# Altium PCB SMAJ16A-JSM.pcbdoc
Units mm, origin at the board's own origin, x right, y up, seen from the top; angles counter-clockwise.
Board outline 19.08 x 15.58 mm, 2 copper layers (Top Layer, Bottom Layer), stack 0 mm thick; 1 components, 0 nets, 2 pads, 0 vias.
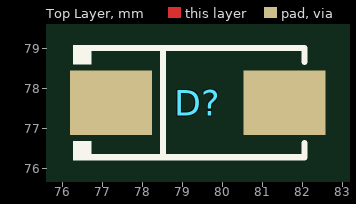
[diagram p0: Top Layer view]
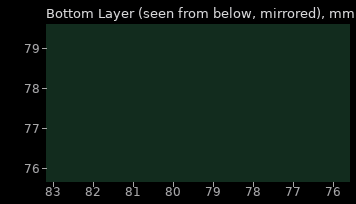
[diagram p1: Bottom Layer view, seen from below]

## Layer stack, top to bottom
Top Layer: signal copper (thickness not stored)
Bottom Layer: signal copper (thickness not stored)

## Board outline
88.935,69.85 69.85,69.85 69.85,85.43 88.935,85.43

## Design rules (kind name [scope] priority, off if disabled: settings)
PasteMaskExpansion "Paste Mask Expansion" [All] p1: expansion=0
SolderMaskExpansion "Solder Mask Expansion" [IsVia] p1: expansion=-25.4 istentingtop=TRUE
SolderMaskExpansion "Solder Mask Expansion" [All] p2: expansion=0.051 istentingtop=FALSE

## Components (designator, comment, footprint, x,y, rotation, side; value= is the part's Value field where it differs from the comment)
D? "SMAJ16A-JSM" SMA_L4.4-W2.6-LS5.1-RD 79.392,77.64 r0 top

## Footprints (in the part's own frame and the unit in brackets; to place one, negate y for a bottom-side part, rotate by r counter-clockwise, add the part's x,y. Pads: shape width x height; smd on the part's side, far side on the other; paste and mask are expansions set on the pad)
SMA_L4.4-W2.6-LS5.1-RD [mm]
  rect 2.046x1.62 smd: 1(-2.169,0) 2(2.169,0)
  silkscreen extent -3.12,-1.44 2.67,1.44

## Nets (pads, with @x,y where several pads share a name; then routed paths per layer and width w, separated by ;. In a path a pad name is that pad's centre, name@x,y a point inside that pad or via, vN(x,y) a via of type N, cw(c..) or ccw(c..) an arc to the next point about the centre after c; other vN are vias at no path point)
pads on no net: D?.1 D?.2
